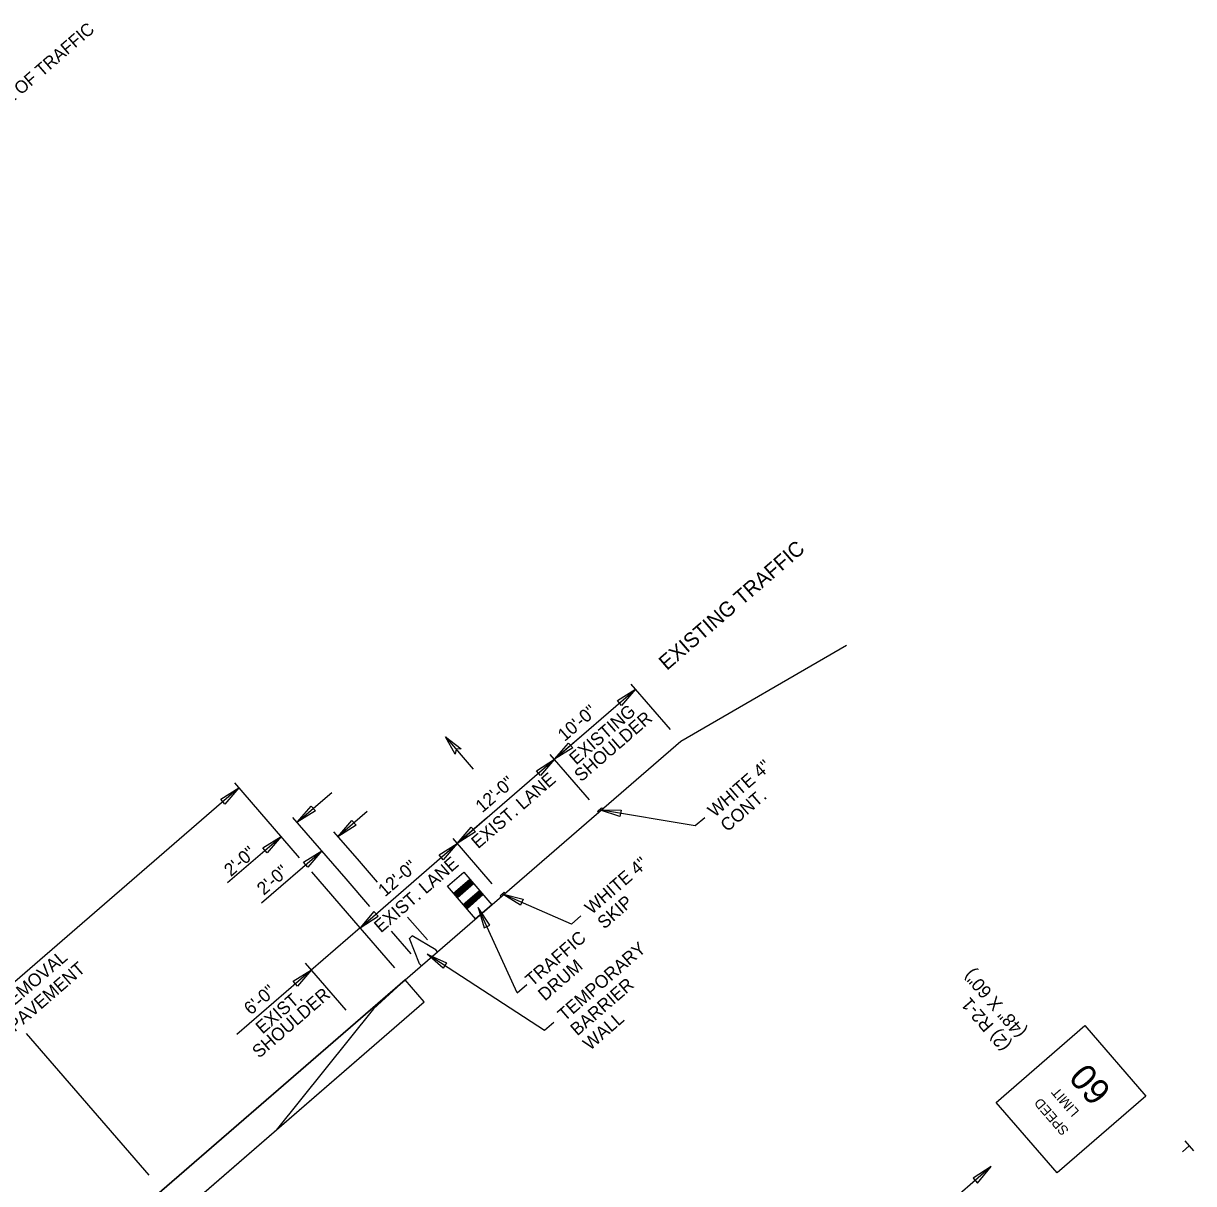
# Model space of a CAD drawing. Extents: x 259983 to 267998, y 211467 to 219827.
# Drawn here: x 266591 to 267683, y 213621 to 214703 of the extents above; entities that cross this region are included whole.
import ezdxf

# ---------------------------------------------------------------- set-up
doc = ezdxf.new("R2010")
doc.units = 0
for name, color, linetype in [('1', 7, 'Continuous'), ('CL', 7, 'Continuous'), ('Default', 7, 'Continuous'), ('Level 1', 7, 'Continuous'), ('Level 43', 7, 'Continuous'), ('Level 58', 7, 'Continuous'), ('R_MOT', 7, 'Continuous'), ('R_MOT STAGE 2', 7, 'Continuous')]:
    doc.layers.add(name, color=color, linetype=linetype)

msp = doc.modelspace()

# ---------------------------------------------------------------- linework, layer by layer
at = {"layer": '1'}
for p, q in [((267086.8, 214016.7), (267162.4, 214082.2)), ((267159.3, 214085.6), (267158.4, 214086.7)), ((267195, 214044.5), (267158.4, 214086.7)), ((267114, 214040.3), (267086.8, 214016.7)), ((266996, 213938.2), (267086.8, 214016.7)), ((267119.4, 213979), (267082.8, 214021.2)), ((266792.3, 213990.1), (266338.7, 213597.4)), ((266848.9, 213924.8), (266788.4, 213994.7)), ((266846.7, 213957.9), (266878.9, 213985.7)), ((266912, 213968.1), (266884.7, 213944.5)), ((267218.1, 213954.5), (267128.7, 213969.6)), ((266892.4, 213905.1), (266842.7, 213962.5)), ((267023.2, 213961.7), (266996, 213938.2)), ((267227, 213962.2), (267218.1, 213954.5)), ((266902.8, 213923.7), (266880.8, 213949)), ((266781.7, 213901.7), (266831.6, 213944.8)), ((266905.3, 213859.6), (266996, 213938.2)), ((267028.6, 213900.5), (266992.1, 213942.7)), ((266813.4, 213882.8), (266869.6, 213931.4)), ((266921.5, 213902), (266902.8, 213923.7)), ((266899.4, 213866.4), (266860.2, 213911.7)), ((266914.5, 213879.5), (266892.4, 213905.1)), ((267102.5, 213863), (267038, 213891.1)), ((266968.1, 213848.2), (266949.6, 213869.5)), ((267052, 213798.9), (267015.4, 213878.5)), ((267111.4, 213870.7), (267102.5, 213863)), ((266905.3, 213859.6), (266790.2, 213760)), ((266937.9, 213822), (266899.4, 213866.4)), ((266953, 213835.1), (266934.5, 213856.4)), ((266892.5, 213782.7), (266854.5, 213826.6)), ((267077.3, 213763.5), (266967.8, 213835)), ((267052, 213798.9), (267060.8, 213806.5)), ((267086.2, 213771.2), (267077.3, 213763.5))]:
    msp.add_line(p, q, dxfattribs=at)
for points in [[(267145.4, 214071.5), (267162.4, 214082.2), (267149.3, 214066.9)], [(267103.7, 214027.4), (267086.8, 214016.7), (267099.8, 214031.9)], [(267069.8, 214006), (267086.8, 214016.7), (267073.7, 214001.5)], [(266775.4, 213979.4), (266792.3, 213990.1), (266779.3, 213974.9)], [(266863.6, 213968.6), (266846.7, 213957.9), (266859.7, 213973.1)], [(267147.8, 213963.4), (267128.7, 213969.6), (267148.8, 213969.3)], [(266901.7, 213955.2), (266884.7, 213944.5), (266897.7, 213959.7)], [(267013, 213948.9), (266996, 213938.2), (267009, 213953.4)], [(266814.6, 213934.1), (266831.6, 213944.8), (266818.5, 213929.5)], [(266979.1, 213927.5), (266996, 213938.2), (266983, 213922.9)], [(266852.7, 213920.7), (266869.6, 213931.4), (266856.6, 213916.2)], [(267055.1, 213880.6), (267038, 213891.1), (267057.4, 213886.2)], [(266918.3, 213874.8), (266905.3, 213859.6), (266922.2, 213870.3)], [(267026.4, 213861.8), (267015.4, 213878.5), (267021, 213859.3)], [(266982.8, 213821.8), (266967.8, 213835), (266986, 213826.8)], [(266843, 213809.7), (266859.9, 213820.3), (266846.9, 213805.1)], [(267481.3, 213621.3), (267494.3, 213636.6), (267477.3, 213625.9)]]:
    msp.add_lwpolyline(points, close=True, dxfattribs=at)
at = {"layer": 'CL'}
msp.add_line((266708.4, 213628.6), (266594, 213760.8), dxfattribs=at)
at = {"layer": 'Default'}
for p, q in [((267204.5, 214033.5), (267359.3, 214123.3)), ((266493.8, 213418.3), (267204.5, 214033.5)), ((266951.3, 213849.6), (266954, 213851.9)), ((266960.9, 213825.9), (266951.3, 213849.6)), ((266976, 213839), (266954, 213851.9)), ((266977.7, 213837.2), (266976, 213839)), ((266962.5, 213824.1), (266960.9, 213826)), ((266947.4, 213811), (266236.7, 213195.7)), ((266947.4, 213811), (266917.9, 213783.8)), ((266965.2, 213790.4), (266947.4, 213811)), ((266511.6, 213397.7), (266965.2, 213790.4)), ((266917.9, 213783.8), (266827, 213670.7))]:
    msp.add_line(p, q, dxfattribs=at)
for points in [[(267126.8, 213967.9), (267130.7, 213971.3), (267131.5, 213970.3), (267127.7, 213967)], [(267036.1, 213889.4), (267039.9, 213892.7), (267040.8, 213891.8), (267036.9, 213888.4)]]:
    msp.add_lwpolyline(points, close=True, dxfattribs=at)
at = {"layer": 'Level 43'}
msp.add_lwpolyline([(266985, 214037.7), (267011, 214007.6)], dxfattribs=at)
at = {"layer": 'Level 58'}
msp.add_lwpolyline([(266994, 214021.6), (266985, 214037.7), (266999.6, 214026.5), (266994.9, 214026.3)], close=True, dxfattribs=at)
at = {"layer": 'R_MOT'}
for p, q in [((266992.6, 213891.7), (267007.7, 213904.8)), ((266993.1, 213891.2), (267008.2, 213904.2)), ((266993.5, 213890.6), (267008.7, 213903.7)), ((266994, 213890.1), (267009.1, 213903.2)), ((266994.5, 213889.5), (267009.6, 213902.6)), ((266995.1, 213888.8), (267010.2, 213901.8)), ((266995.7, 213888.1), (267010.8, 213901.2)), ((266996.1, 213887.6), (267011.2, 213900.7)), ((267001.5, 213881.3), (267016.7, 213894.4)), ((267002, 213880.8), (267017.1, 213893.9)), ((267002.5, 213880.2), (267017.6, 213893.3)), ((267002.9, 213879.7), (267018.1, 213892.8)), ((267003.5, 213879.1), (267018.6, 213892.2)), ((267004.1, 213878.4), (267019.2, 213891.5)), ((267004.7, 213877.7), (267019.8, 213890.8)), ((267005.1, 213877.3), (267020.2, 213890.4)), ((267679, 213656.1), (267672.6, 213650.5)), ((267675, 213660.7), (267683, 213651.5))]:
    msp.add_line(p, q, dxfattribs=at)
for points in [[(266987, 213898.2), (267002.1, 213911.3), (267028.3, 213881), (267013.1, 213867.9)], [(267498.8, 213696.5), (267581.7, 213768.2), (267638.5, 213702.4), (267555.7, 213630.8)]]:
    msp.add_lwpolyline(points, close=True, dxfattribs=at)
at = {"layer": 'R_MOT STAGE 2'}
msp.add_line((267494.3, 213636.6), (267309.9, 213476.9), dxfattribs=at)
msp.add_lwpolyline([(266493.8, 213418.3), (266511.6, 213397.7), (266965.2, 213790.4), (266947.4, 213811)], close=True, dxfattribs=at)

# ---------------------------------------------------------------- texts
at = {"layer": '1'}
for s, height, rotation, p in [('EXISTING TRAFFIC', 14, 40.8733, (267191.6, 214099.1)), ('10\'-0"', 12, 40.8833, (267096.2, 214032.8)), ('EXISTING', 12, 40.8833, (267106.9, 214010.9)), ('SHOULDER', 12, 40.8833, (267111.6, 213995.1)), ('WHITE 4"', 12, 40.8833, (267236.2, 213962)), ('EXIST. LANE', 12, 40.8833, (267015.5, 213932.7)), ('12\'-0"', 12, 40.8833, (267019.4, 213966.3)), ('CONT.', 12, 40.8833, (267248, 213948.4)), ('2\'-0"', 12, 40.8733, (266784.8, 213906.7)), ('EXIST. LANE', 12, 40.8833, (266924.8, 213854.2)), ('WHITE 4"', 12, 40.8833, (267121.4, 213871.3)), ('2\'-0"', 12, 40.8733, (266815.5, 213889.3)), ('12\'-0"', 12, 40.8833, (266928.6, 213887.8)), ('SKIP', 12, 40.8833, (267133.2, 213857.7)), ('TRAFFIC', 12, 40.8833, (267066, 213804.2)), ('TEMPORARY', 12, 40.8833, (267096.2, 213771.7)), ('STAGE 4B REMOVAL', 12, 40.8833, (266511.3, 213724.7)), ('OF M.O.T. PAVEMENT', 12, 40.8833, (266522.5, 213709.3)), ('DRUM', 12, 40.8833, (267077.8, 213790.6)), ('6\'-0"', 12, 40.8833, (266803.4, 213777.5)), ('BARRIER', 12, 40.8833, (267108, 213758.1)), ('SHOULDER', 12, 40.8833, (266811.1, 213737.2)), ('EXIST.', 12, 40.8833, (266814.3, 213759.8)), ('WALL', 12, 40.8833, (267119.8, 213744.5))]:
    msp.add_text(s, height=height, rotation=rotation, dxfattribs=at).set_placement(p)
at = {"layer": 'Level 1'}
msp.add_text('MAINTENANCE OF TRAFFIC', height=11.7, rotation=40.8733, dxfattribs=at).set_placement((266499.4, 214558.7))
at = {"layer": 'R_MOT'}
for s, height, p in [('(48" X 60")', 12.129, (267527.7, 213763)), ('(2) R2-1', 12.13, (267513.2, 213750.5)), ('60', 24.26, (267607.4, 213707.6)), ('LIMIT', 9.05, (267576.8, 213688.1)), ('SPEED', 9.05, (267567.2, 213670.6))]:
    msp.add_text(s, height=height, rotation=130.8555, dxfattribs=at).set_placement(p)

doc.saveas('drawing.dxf')
